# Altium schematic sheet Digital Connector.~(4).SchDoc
size A
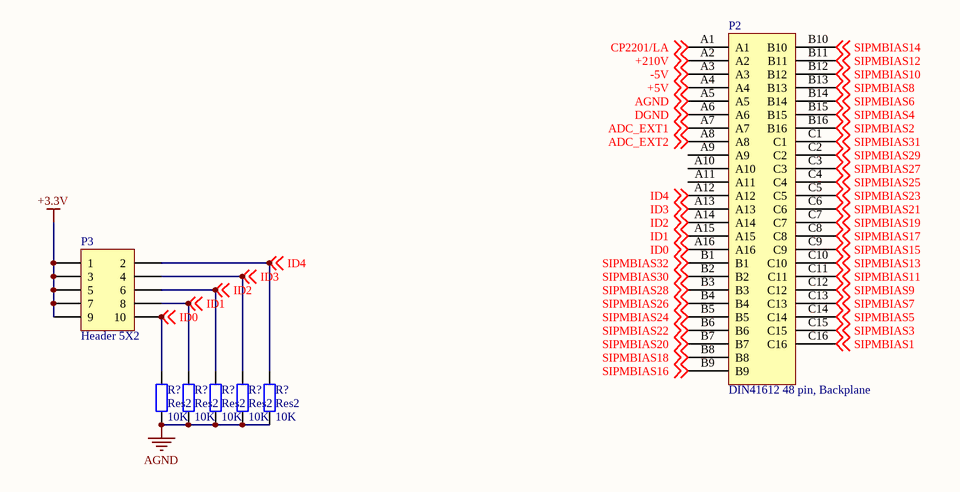
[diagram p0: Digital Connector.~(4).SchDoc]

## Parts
(Parts that share a designator on the sheet are numbered #1, #2 ... from top to bottom, then left to right.)
P2  DIN41612 48 pin, Backplane  [EURO2.54-2V48]
P3  Header 5X2  [HDR2X5]
R?#1  Res2  value 10K  [1005[0402]]
R?#2  Res2  value 10K  [1005[0402]]
R?#3  Res2  value 10K  [1005[0402]]
R?#4  Res2  value 10K  [1005[0402]]
R?#5  Res2  value 10K  [1005[0402]]

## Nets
+3.3V: P3.1 P3.3 P3.5 P3.7 P3.9
AGND: P2.A5 R?#1.1 R?#2.1 R?#3.1 R?#4.1 R?#5.1 ; off-sheet AGND
+5V: P2.A4 ; off-sheet +5V
+210V: P2.A2 ; off-sheet +210V
-5V: P2.A3 ; off-sheet -5V
ADC_EXT1: P2.A7 ; off-sheet ADC_EXT1
ADC_EXT2: P2.A8 ; off-sheet ADC_EXT2
CP2201/LA: P2.A1 ; off-sheet CP2201/LA
DGND: P2.A6 ; off-sheet DGND
ID0: P2.A16 P3.10 R?#1.2 ; off-sheet ID0
ID1: P2.A15 P3.8 R?#2.2 ; off-sheet ID1
ID2: P2.A14 P3.6 R?#3.2 ; off-sheet ID2
ID3: P2.A13 P3.4 R?#4.2 ; off-sheet ID3
ID4: P2.A12 P3.2 R?#5.2 ; off-sheet ID4
SIPMBIAS1: P2.C16 ; off-sheet SIPMBIAS1
SIPMBIAS2: P2.B16 ; off-sheet SIPMBIAS2
SIPMBIAS3: P2.C15 ; off-sheet SIPMBIAS3
SIPMBIAS4: P2.B15 ; off-sheet SIPMBIAS4
SIPMBIAS5: P2.C14 ; off-sheet SIPMBIAS5
SIPMBIAS6: P2.B14 ; off-sheet SIPMBIAS6
SIPMBIAS7: P2.C13 ; off-sheet SIPMBIAS7
SIPMBIAS8: P2.B13 ; off-sheet SIPMBIAS8
SIPMBIAS9: P2.C12 ; off-sheet SIPMBIAS9
SIPMBIAS10: P2.B12 ; off-sheet SIPMBIAS10
SIPMBIAS11: P2.C11 ; off-sheet SIPMBIAS11
SIPMBIAS12: P2.B11 ; off-sheet SIPMBIAS12
SIPMBIAS13: P2.C10 ; off-sheet SIPMBIAS13
SIPMBIAS14: P2.B10 ; off-sheet SIPMBIAS14
SIPMBIAS15: P2.C9 ; off-sheet SIPMBIAS15
SIPMBIAS16: P2.B9 ; off-sheet SIPMBIAS16
SIPMBIAS17: P2.C8 ; off-sheet SIPMBIAS17
SIPMBIAS18: P2.B8 ; off-sheet SIPMBIAS18
SIPMBIAS19: P2.C7 ; off-sheet SIPMBIAS19
SIPMBIAS20: P2.B7 ; off-sheet SIPMBIAS20
SIPMBIAS21: P2.C6 ; off-sheet SIPMBIAS21
SIPMBIAS22: P2.B6 ; off-sheet SIPMBIAS22
SIPMBIAS23: P2.C5 ; off-sheet SIPMBIAS23
SIPMBIAS24: P2.B5 ; off-sheet SIPMBIAS24
SIPMBIAS25: P2.C4 ; off-sheet SIPMBIAS25
SIPMBIAS26: P2.B4 ; off-sheet SIPMBIAS26
SIPMBIAS27: P2.C3 ; off-sheet SIPMBIAS27
SIPMBIAS28: P2.B3 ; off-sheet SIPMBIAS28
SIPMBIAS29: P2.C2 ; off-sheet SIPMBIAS29
SIPMBIAS30: P2.B2 ; off-sheet SIPMBIAS30
SIPMBIAS31: P2.C1 ; off-sheet SIPMBIAS31
SIPMBIAS32: P2.B1 ; off-sheet SIPMBIAS32

Not connected (* = marked no-connect by the designer): P2 A9 A10 A11

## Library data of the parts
P3 = Header 5X2: Header, 5-Pin, Dual row
R?#1-R?#5 = Res2: Resistor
